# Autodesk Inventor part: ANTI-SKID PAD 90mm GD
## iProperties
Created: 2007-03
Part Number: ANTI-SKID PAD 90mm GD
Document SubType Name: Modeling
Designer: Andy Moles
Material: Rubber
Density: 0.93 g/cm^3
Author: Andy Moles
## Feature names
1. Revolution1
